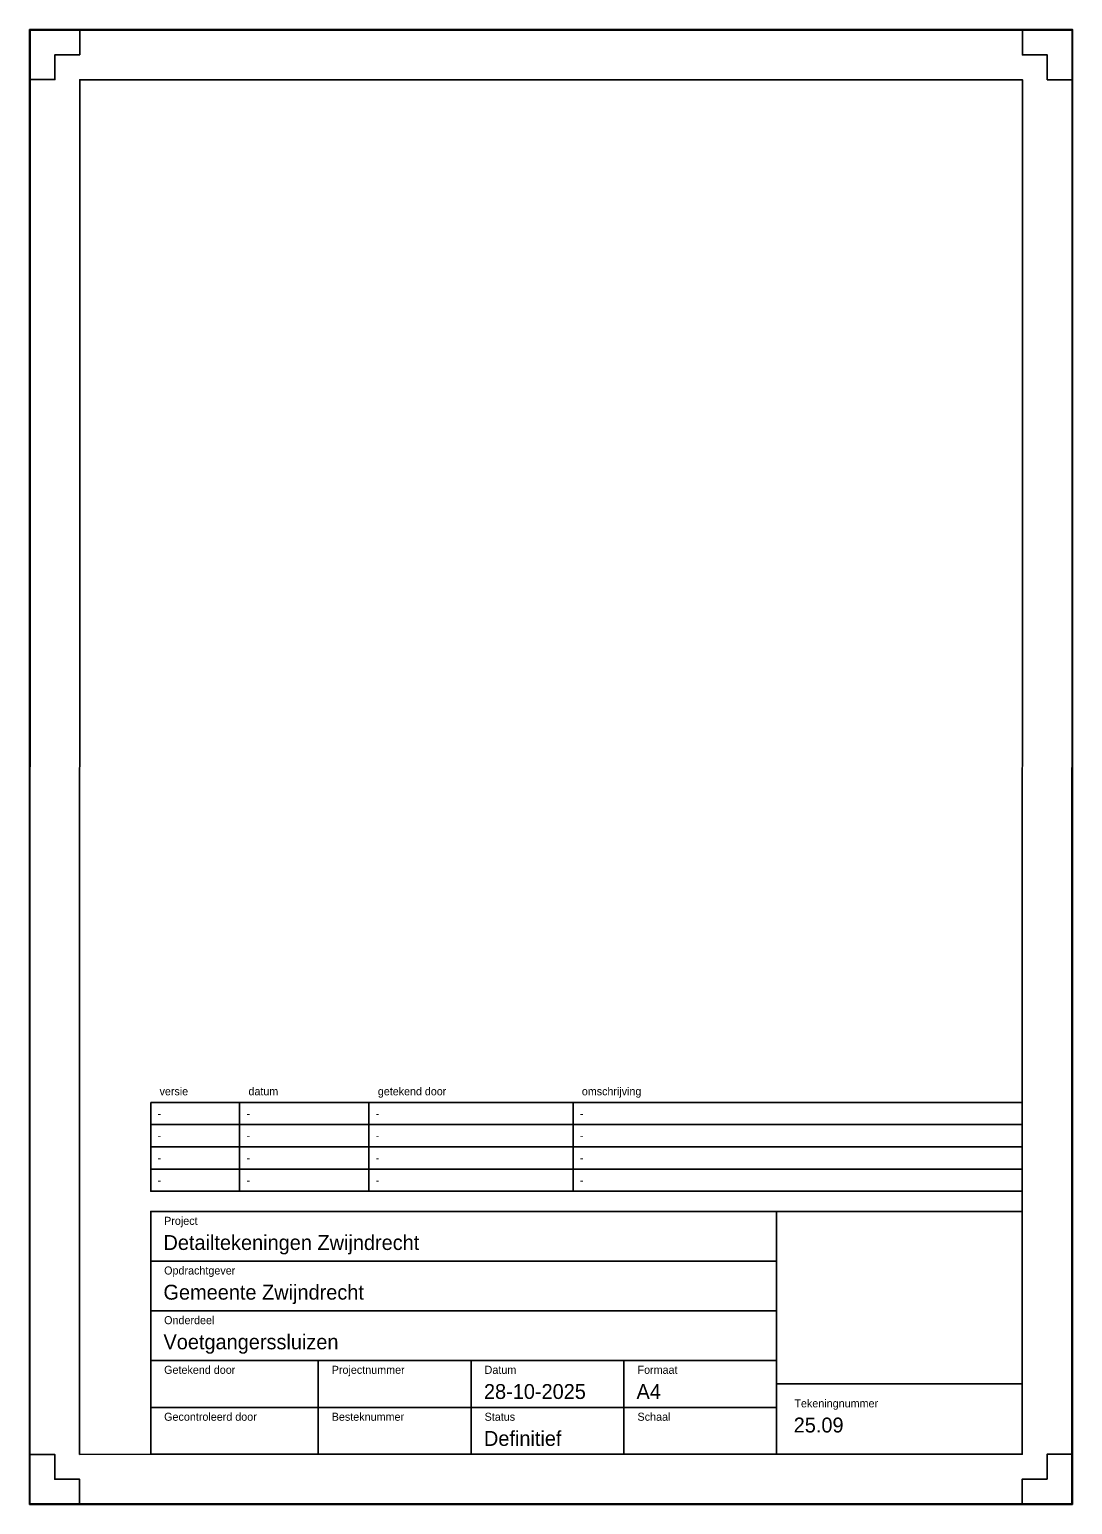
# Model space of a CAD drawing. Extents: x -1 to 209, y -1 to 296.
import ezdxf

# ---------------------------------------------------------------- set-up
doc = ezdxf.new("R2010")
doc.units = 0
for name, color, linetype in [('63', 7, 'Continuous'), ('Tekeningenhoofd', 7, 'Continuous'), ('X-XX-AL-TEKENBLAD_KADER-G', 7, 'Continuous'), ('X-XX-AL-TEKENBLAD_KADER_AFSNIJMARKERING-G', 7, 'Continuous'), ('X-XX-AL-TEKENBLAD_TITELBLOK-T', 7, 'Continuous'), ('X-XX-AL-TEKENBLAD_TITELBLOK_DIK-G', 7, 'Continuous'), ('X-XX-AL-TEKENBLAD_TITELBLOK_DUN-G', 7, 'Continuous')]:
    doc.layers.add(name, color=color, linetype=linetype)

msp = doc.modelspace()

# ---------------------------------------------------------------- linework, layer by layer
at = {"layer": '63'}
msp.add_lwpolyline([(-0.8, -0.8), (209.21, -0.79), (209.22, 296.21), (-0.77, 296.2)], close=True, dxfattribs=at)
at = {"layer": 'X-XX-AL-TEKENBLAD_KADER-G'}
for points in [[(-0.7, -0.7), (209.11, -0.69), (209.12, 296.11), (-0.67, 296.1)], [(9.3, 9.3), (199.11, 9.31), (199.12, 286.11), (9.33, 286.1)]]:
    msp.add_lwpolyline(points, close=True, dxfattribs=at)
at = {"layer": 'X-XX-AL-TEKENBLAD_KADER_AFSNIJMARKERING-G'}
for points in [[(-0.69, 286.14), (4.31, 286.14), (4.31, 291.14), (9.31, 291.14), (9.31, 296.14), (-0.69, 296.14)], [(209.12, 286.11), (204.12, 286.11), (204.12, 291.11), (199.12, 291.11), (199.12, 296.11), (209.12, 296.11)], [(-0.7, 9.3), (4.3, 9.3), (4.3, 4.3), (9.3, 4.3), (9.3, -0.7), (-0.7, -0.7)], [(209.11, 9.31), (204.11, 9.31), (204.11, 4.31), (199.11, 4.31), (199.11, -0.69), (209.11, -0.69)]]:
    msp.add_lwpolyline(points, close=True, dxfattribs=at)
for points in [[(4.31, 291.14), (9.31, 291.14), (9.31, 296.14), (-0.69, 296.14), (-0.69, 286.14), (4.31, 286.14), (4.31, 291.14), (4.31, 291.14)], [(204.12, 291.11), (199.12, 291.11), (199.12, 296.11), (209.12, 296.11), (209.12, 286.11), (204.12, 286.11), (204.12, 291.11), (204.12, 291.11)], [(4.3, 4.3), (9.3, 4.3), (9.3, -0.7), (-0.7, -0.7), (-0.7, 9.3), (4.3, 9.3), (4.3, 4.3), (4.3, 4.3)], [(204.11, 4.31), (199.11, 4.31), (199.11, -0.69), (209.11, -0.69), (209.11, 9.31), (204.11, 9.31), (204.11, 4.31), (204.11, 4.31)]]:
    msp.add_lwpolyline(points, dxfattribs=at)
at = {"layer": 'X-XX-AL-TEKENBLAD_TITELBLOK_DIK-G'}
msp.add_lwpolyline([(199.11, 9.31), (23.61, 9.31), (23.61, 58.21), (199.11, 58.21)], close=True, dxfattribs=at)
at = {"layer": 'X-XX-AL-TEKENBLAD_TITELBLOK_DUN-G'}
for p, q in [((41.51, 80.17), (41.51, 75.7)), ((67.56, 80.17), (67.56, 75.7)), ((108.65, 80.17), (108.65, 75.7)), ((41.51, 75.7), (41.51, 71.22)), ((67.56, 75.7), (67.56, 71.22)), ((108.65, 75.7), (108.65, 71.22)), ((41.51, 71.22), (41.51, 66.75)), ((67.56, 71.22), (67.56, 66.75)), ((108.65, 71.22), (108.65, 66.75)), ((41.51, 66.75), (41.51, 62.27)), ((67.56, 66.75), (67.56, 62.27)), ((108.65, 66.75), (108.65, 62.27)), ((193.68, 62.27), (23.61, 62.27)), ((149.61, 9.31), (149.61, 58.21)), ((23.61, 48.21), (149.61, 48.21)), ((23.61, 38.21), (149.61, 38.21)), ((23.61, 28.21), (149.61, 28.21)), ((57.36, 9.31), (57.36, 28.21)), ((88.11, 9.31), (88.11, 28.21)), ((118.86, 9.31), (118.86, 28.21)), ((149.61, 23.49), (199.11, 23.49)), ((23.61, 18.76), (149.61, 18.76))]:
    msp.add_line(p, q, dxfattribs=at)
for points in [[(23.61, 80.17), (199.11, 80.17), (199.11, 75.7), (23.61, 75.7)], [(23.61, 75.7), (199.11, 75.7), (199.11, 71.22), (23.61, 71.22)], [(23.61, 71.22), (199.11, 71.22), (199.11, 66.75), (23.61, 66.75)], [(23.61, 66.75), (199.11, 66.75), (199.11, 62.27), (23.61, 62.27)]]:
    msp.add_lwpolyline(points, close=True, dxfattribs=at)

# ---------------------------------------------------------------- texts
at = {"layer": 'Tekeningenhoofd'}
for s, height, p in [('versie', 1.611, (25.4, 81.6)), ('datum', 1.611, (43.3, 81.6)), ('getekend door', 1.6112, (69.35, 81.6)), ('omschrijving', 1.6112, (110.43, 81.6))]:
    msp.add_text(s, height=height, dxfattribs=at).set_placement(p)
at = {"layer": 'X-XX-AL-TEKENBLAD_TITELBLOK-T'}
for s, height, p in [('Project', 1.62, (26.31, 55.51)), ('Detailtekeningen Zwijndrecht', 3, (26.18, 50.45)), ('Opdrachtgever', 1.62, (26.31, 45.51)), ('Gemeente Zwijndrecht', 3, (26.18, 40.45)), ('Onderdeel', 1.62, (26.31, 35.51)), ('Voetgangerssluizen', 3, (26.18, 30.45)), ('Getekend door', 1.62, (26.31, 25.51)), ('Projectnummer', 1.62, (60.06, 25.51)), ('Datum', 1.62, (90.84, 25.51)), ('Formaat', 1.62, (121.63, 25.51)), ('28-10-2025', 3, (90.71, 20.45)), ('A4', 3, (121.43, 20.45)), ('Tekeningnummer', 1.62, (153.22, 18.76)), ('Gecontroleerd door', 1.62, (26.31, 16.06)), ('Besteknummer', 1.62, (60.06, 16.06)), ('Status', 1.62, (90.84, 16.06)), ('Schaal', 1.62, (121.63, 16.06)), ('25.09', 3, (153.08, 13.7)), ('Definitief', 3, (90.71, 11))]:
    msp.add_text(s, height=height, dxfattribs=at).set_placement(p)
at = {"layer": 'X-XX-AL-TEKENBLAD_TITELBLOK_DUN-G'}
for p in [(24.97, 77.13), (42.88, 77.13), (68.92, 77.13), (110.01, 77.13), (24.97, 72.65), (42.88, 72.65), (68.92, 72.65), (110.01, 72.65), (24.97, 68.18), (42.88, 68.18), (68.92, 68.18), (110.01, 68.18), (24.97, 63.7), (42.88, 63.7), (68.92, 63.7), (110.01, 63.7)]:
    msp.add_text('-', height=1.61, dxfattribs=at).set_placement(p)

doc.saveas('drawing.dxf')
